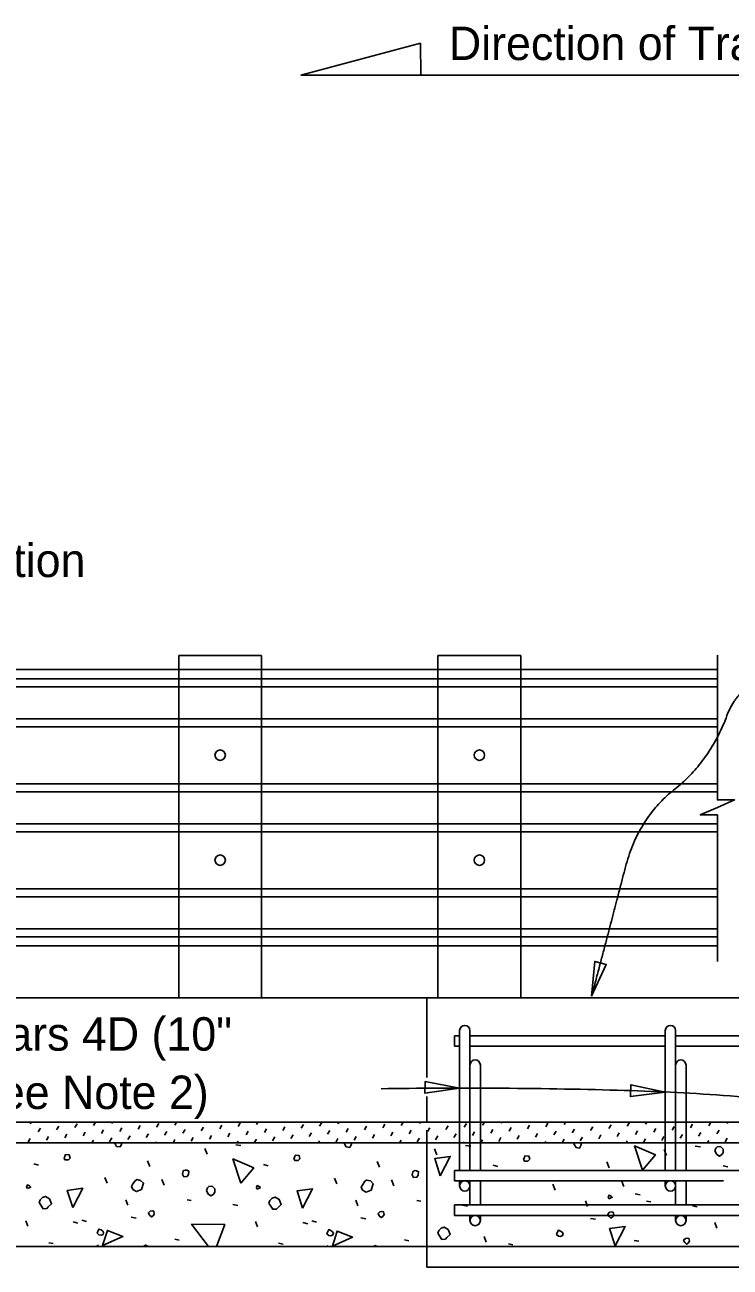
# Model space of a CAD drawing. Extents: x 0 to 41.1, y 0 to 25.9.
# Drawn here: x 33.37 to 37.62, y 6.24 to 13.74 of the extents above; entities that cross this region are included whole.
import ezdxf

# ---------------------------------------------------------------- set-up
doc = ezdxf.new("R2010")
doc.units = 0
for name, color, linetype in [('Dimension', 7, 'Continuous'), ('ExistSuperStruct', 7, 'Continuous'), ('Miscellaneous', 7, 'Continuous'), ('Rebar', 7, 'Continuous'), ('SteelMisc_h', 7, 'Continuous'), ('SubStrConc', 7, 'Continuous'), ('SubStrConc_h', 7, 'Continuous'), ('TextStructures', 7, 'Continuous')]:
    doc.layers.add(name, color=color, linetype=linetype)

msp = doc.modelspace()

# ---------------------------------------------------------------- linework, layer by layer
at = {"layer": 'Dimension'}
for p, q in [((35.0367, 13.433), (35.7584, 13.6246)), ((35.7584, 13.6246), (35.76, 13.433)), ((38.8471, 13.433), (35.0367, 13.433)), ((35.76, 13.433), (38.9734, 13.433))]:
    msp.add_line(p, q, dxfattribs=at)
msp.add_lwpolyline([(37.5468, 8.0879), (37.5468, 8.9711), (37.4435, 8.9711), (37.5468, 9.0161), (37.6502, 9.0611), (37.5468, 9.0611), (37.5468, 9.9341)], dxfattribs=at)
for points in [[(36.7889, 7.8777), (36.8763, 8.07), (36.8081, 8.0881)], [(35.9929, 7.3234), (35.7855, 7.3634), (35.7839, 7.2929)], [(37.2319, 7.2993), (37.0254, 7.3435), (37.0223, 7.273)]]:
    msp.add_lwpolyline(points, close=True, dxfattribs=at)
for points, degree in [([(38.2272, 9.8963), (37.7131, 9.8611), (37.5023, 9.2938), (37.0685, 8.9512), (36.9144, 8.3516), (36.7889, 7.8777)], 2), ([(38.4751, 7.1982), (37.7447, 7.2724), (37.1209, 7.3194), (35.9507, 7.3277), (35.5209, 7.3197)], 3)]:
    msp.add_open_spline(points, degree=degree, dxfattribs=at)
at = {"layer": 'ExistSuperStruct'}
for p, q in [((27.6853, 7.8689), (35.7954, 7.8689)), ((39.26, 7.1191), (27.6853, 7.1191)), ((27.6853, 6.994), (39.26, 6.994)), ((39.26, 6.369), (32.9053, 6.369))]:
    msp.add_line(p, q, dxfattribs=at)
at = {"layer": 'Miscellaneous'}
for p, q in [((34.2999, 9.9315), (34.2999, 7.869)), ((34.2999, 9.9315), (34.7999, 9.9315)), ((34.7999, 9.9315), (34.7999, 7.869)), ((35.8624, 9.9315), (35.8624, 7.869)), ((35.8624, 9.9315), (36.3624, 9.9315)), ((36.3624, 9.9315), (36.3624, 7.869)), ((26.2319, 9.7925), (37.5468, 9.7925)), ((26.2319, 9.7443), (37.5468, 9.7443)), ((26.2319, 9.5515), (37.5468, 9.5515)), ((26.2319, 9.5032), (37.5468, 9.5032)), ((26.2319, 9.1593), (37.5468, 9.1593)), ((26.2319, 9.1111), (37.5468, 9.1111)), ((26.2319, 8.9182), (37.5468, 8.9182)), ((26.2319, 8.8701), (37.5468, 8.8701)), ((26.2319, 8.5262), (37.5468, 8.5262)), ((26.2319, 8.4779), (37.5468, 8.4779)), ((26.2319, 8.2851), (37.5468, 8.2851)), ((26.2319, 8.2369), (37.5468, 8.2369)), ((33.4048, 7.108), (33.4112, 7.1191)), ((33.7856, 7.0981), (33.7977, 7.1191)), ((33.8962, 7.1111), (33.9008, 7.1191)), ((34.2769, 7.1011), (34.2873, 7.1191)), ((34.3876, 7.1141), (34.3904, 7.1191)), ((34.7683, 7.1041), (34.7769, 7.1191)), ((34.8789, 7.1171), (34.8801, 7.1191)), ((35.2597, 7.1072), (35.2666, 7.1191)), ((35.6404, 7.0972), (35.653, 7.1191)), ((35.751, 7.1102), (35.7562, 7.1191)), ((36.1318, 7.1002), (36.1427, 7.1191)), ((36.2424, 7.1132), (36.2458, 7.1191)), ((36.6231, 7.1032), (36.6323, 7.1191)), ((36.7338, 7.1162), (36.7354, 7.1191)), ((37.1145, 7.1063), (37.1219, 7.1191)), ((37.4952, 7.0963), (37.5082, 7.1187)), ((37.6058, 7.1093), (37.6115, 7.1191)), ((33.4537, 7.0592), (33.4666, 7.0816)), ((33.5643, 7.0722), (33.5773, 7.0946)), ((33.6131, 7.0233), (33.6261, 7.0457)), ((33.6749, 7.0851), (33.6879, 7.1075)), ((33.7238, 7.0363), (33.7367, 7.0587)), ((33.8344, 7.0493), (33.8474, 7.0717)), ((33.945, 7.0622), (33.958, 7.0846)), ((34.0557, 7.0752), (34.0686, 7.0976)), ((34.1045, 7.0264), (34.1175, 7.0487)), ((34.1663, 7.0881), (34.1793, 7.1105)), ((34.2151, 7.0393), (34.2281, 7.0617)), ((34.3258, 7.0523), (34.3387, 7.0747)), ((34.4364, 7.0652), (34.4494, 7.0876)), ((34.547, 7.0782), (34.56, 7.1006)), ((34.5959, 7.0294), (34.6088, 7.0518)), ((34.6577, 7.0912), (34.6706, 7.1136)), ((34.7065, 7.0423), (34.7195, 7.0647)), ((34.8171, 7.0553), (34.8301, 7.0777)), ((34.9278, 7.0683), (34.9407, 7.0907)), ((35.0384, 7.0812), (35.0514, 7.1036)), ((35.0872, 7.0324), (35.1002, 7.0548)), ((35.149, 7.0942), (35.162, 7.1166)), ((35.1979, 7.0454), (35.2108, 7.0677)), ((35.3085, 7.0583), (35.3215, 7.0807)), ((35.4191, 7.0713), (35.4321, 7.0937)), ((35.468, 7.0224), (35.4809, 7.0448)), ((35.5298, 7.0842), (35.5427, 7.1066)), ((35.5786, 7.0354), (35.5916, 7.0578)), ((35.6892, 7.0484), (35.7022, 7.0708)), ((35.7999, 7.0613), (35.8128, 7.0837)), ((35.9105, 7.0743), (35.9234, 7.0967)), ((35.9593, 7.0255), (35.9723, 7.0479)), ((36.0211, 7.0873), (36.0341, 7.1097)), ((36.07, 7.0384), (36.0829, 7.0608)), ((36.1806, 7.0514), (36.1935, 7.0738)), ((36.2912, 7.0644), (36.3042, 7.0867)), ((36.4019, 7.0773), (36.4148, 7.0997)), ((36.4507, 7.0285), (36.4636, 7.0509)), ((36.5125, 7.0903), (36.5254, 7.1127)), ((36.5613, 7.0415), (36.5743, 7.0638)), ((36.672, 7.0544), (36.6849, 7.0768)), ((36.7826, 7.0674), (36.7955, 7.0898)), ((36.8932, 7.0803), (36.9062, 7.1027)), ((36.9421, 7.0315), (36.955, 7.0539)), ((37.0039, 7.0933), (37.0168, 7.1157)), ((37.0527, 7.0445), (37.0656, 7.0669)), ((37.1633, 7.0574), (37.1763, 7.0798)), ((37.274, 7.0704), (37.2869, 7.0928)), ((37.3228, 7.0216), (37.3357, 7.044)), ((37.3846, 7.0834), (37.3975, 7.1058)), ((37.4334, 7.0345), (37.4464, 7.0569)), ((37.5441, 7.0475), (37.557, 7.0699)), ((33.3919, 6.9974), (33.4048, 7.0198)), ((33.5025, 7.0104), (33.5155, 7.0328)), ((33.6733, 6.994), (33.6749, 6.9969)), ((33.7764, 6.994), (33.7856, 7.0099)), ((33.8832, 7.0004), (33.8962, 7.0228)), ((33.9939, 7.0134), (34.0068, 7.0358)), ((34.1629, 6.994), (34.1663, 6.9999)), ((34.266, 6.994), (34.2769, 7.0129)), ((34.3746, 7.0034), (34.3876, 7.0258)), ((34.4852, 7.0164), (34.4982, 7.0388)), ((34.6436, 6.981), (34.6755, 6.9774)), ((34.6525, 6.994), (34.6577, 7.0029)), ((34.7556, 6.994), (34.7683, 7.0159)), ((34.866, 7.0065), (34.8789, 7.0289)), ((34.9766, 7.0194), (34.9896, 7.0418)), ((35.1421, 6.994), (35.149, 7.0059)), ((35.2467, 6.9965), (35.2597, 7.0189)), ((35.3573, 7.0095), (35.3703, 7.0319)), ((35.5286, 6.994), (35.5298, 6.996)), ((35.6317, 6.994), (35.6404, 7.009)), ((35.7381, 6.9995), (35.751, 7.0219)), ((35.8487, 7.0125), (35.8617, 7.0349)), ((36.0182, 6.994), (36.0211, 6.999)), ((36.0283, 6.9774), (36.0601, 6.9739)), ((36.1213, 6.994), (36.1318, 7.012)), ((36.2294, 7.0026), (36.2424, 7.025)), ((36.3401, 7.0155), (36.353, 7.0379)), ((36.5078, 6.994), (36.5125, 7.002)), ((36.611, 6.994), (36.6231, 7.015)), ((36.7208, 7.0056), (36.7338, 7.028)), ((36.8314, 7.0185), (36.8444, 7.0409)), ((36.9975, 6.994), (37.0039, 7.0051)), ((37.1015, 6.9956), (37.1145, 7.018)), ((37.2122, 7.0086), (37.2251, 7.031)), ((37.3839, 6.994), (37.3846, 6.9951)), ((37.413, 6.9739), (37.4448, 6.9704)), ((37.4871, 6.994), (37.4952, 7.0081)), ((37.5929, 6.9987), (37.6058, 7.021)), ((34.471, 6.925), (34.4569, 6.9604)), ((35.8557, 6.9215), (35.8416, 6.9568)), ((37.2404, 6.918), (37.2262, 6.9533)), ((33.4269, 6.8661), (33.4552, 6.859)), ((34.1252, 6.8502), (34.111, 6.8855)), ((34.8116, 6.8625), (34.8399, 6.8555)), ((35.5099, 6.8466), (35.4957, 6.882)), ((36.1963, 6.859), (36.2245, 6.8519)), ((36.8945, 6.8431), (36.8804, 6.8784)), ((37.5809, 6.8555), (37.6092, 6.8484)), ((33.8689, 6.7494), (33.8547, 6.7847)), ((34.2129, 6.7376), (34.1988, 6.773)), ((35.2535, 6.7459), (35.2394, 6.7812)), ((35.5976, 6.7341), (35.5835, 6.7695)), ((36.5698, 6.7081), (36.5556, 6.7434)), ((36.9823, 6.7306), (36.9682, 6.7659)), ((37.0508, 6.6858), (37.0809, 6.6805)), ((33.9944, 6.6168), (33.982, 6.6504)), ((34.3508, 6.6493), (34.3756, 6.6457)), ((34.6266, 6.621), (34.6566, 6.6157)), ((35.379, 6.6133), (35.3667, 6.6469)), ((35.7355, 6.6457), (35.7603, 6.6422)), ((36.0113, 6.6174), (36.0413, 6.6121)), ((36.7637, 6.6097), (36.7513, 6.6433)), ((37.1202, 6.6422), (37.1449, 6.6387)), ((37.396, 6.6139), (37.426, 6.6086)), ((33.3904, 6.4902), (33.378, 6.5237)), ((33.7168, 6.5267), (33.7451, 6.5196)), ((34.0132, 6.545), (34.0432, 6.5397)), ((34.7751, 6.4866), (34.7627, 6.5202)), ((35.1015, 6.5231), (35.1298, 6.516)), ((35.3979, 6.5414), (35.4279, 6.5361)), ((36.7825, 6.5379), (36.8126, 6.5326)), ((33.6644, 6.5167), (33.6927, 6.5096)), ((35.0491, 6.5131), (35.0774, 6.5061)), ((37.5444, 6.4796), (37.5321, 6.5131)), ((33.5177, 6.3912), (33.5442, 6.3859)), ((33.8137, 6.369), (33.8105, 6.3776)), ((34.2766, 6.4124), (34.3031, 6.4071)), ((34.9024, 6.3876), (34.9289, 6.3823)), ((35.1971, 6.369), (35.1952, 6.3741)), ((35.6613, 6.4088), (35.6878, 6.4035)), ((36.1541, 6.3946), (36.1417, 6.4282)), ((36.287, 6.3841), (36.3136, 6.3788)), ((36.5805, 6.369), (36.5799, 6.3706)), ((37.0459, 6.4053), (37.0725, 6.4))]:
    msp.add_line(p, q, dxfattribs=at)
for points in [[(33.9136, 6.994), (33.9166, 6.988)], [(33.9166, 6.988), (33.9254, 6.9721), (33.9466, 6.9686), (33.9555, 6.9845), (33.9578, 6.994)], [(35.2985, 6.994), (35.2977, 6.9916), (35.3013, 6.9845)], [(35.3013, 6.9845), (35.3101, 6.9686), (35.3313, 6.9651), (35.3401, 6.981), (35.3434, 6.994)], [(36.6844, 6.994), (36.6824, 6.988), (36.6859, 6.981)], [(36.6859, 6.981), (36.6948, 6.9651), (36.716, 6.9615), (36.7248, 6.9774), (36.7284, 6.9916), (36.7259, 6.994)], [(37.0957, 6.8285), (37.048, 6.9753), (37.1735, 6.9205), (37.0957, 6.8285)], [(37.5322, 6.9448), (37.5428, 6.9236), (37.5605, 6.913), (37.5746, 6.9236), (37.5817, 6.9342), (37.5817, 6.9554), (37.5658, 6.9713), (37.5463, 6.9696), (37.5375, 6.9607), (37.5322, 6.9448)], [(33.6143, 6.8908), (33.6355, 6.8908), (33.6461, 6.9014), (33.6408, 6.9209), (33.6178, 6.9226), (33.6143, 6.912), (33.609, 6.9032), (33.6143, 6.8908), (33.6108, 6.8944)], [(34.6743, 6.75), (34.6266, 6.8967), (34.7521, 6.8419), (34.6743, 6.75)], [(34.999, 6.8873), (35.0202, 6.8873), (35.0308, 6.8979), (35.0255, 6.9173), (35.0025, 6.9191), (34.999, 6.9085), (34.9937, 6.8997), (34.999, 6.8873), (34.9954, 6.8908)], [(35.8765, 6.7947), (35.8429, 6.899), (35.9366, 6.9113), (35.8765, 6.7947)], [(36.3836, 6.8837), (36.4049, 6.8837), (36.4155, 6.8944), (36.4102, 6.9138), (36.3872, 6.9156), (36.3836, 6.905), (36.3783, 6.8961), (36.3836, 6.8837), (36.3801, 6.8873)], [(34.3225, 6.8048), (34.3314, 6.7889), (34.3508, 6.7907), (34.3597, 6.8031), (34.3614, 6.8225), (34.3491, 6.8278), (34.3402, 6.8296), (34.3296, 6.826), (34.3261, 6.8225), (34.3225, 6.8048)], [(35.7072, 6.8013), (35.7161, 6.7854), (35.7355, 6.7871), (35.7443, 6.7995), (35.7461, 6.819), (35.7337, 6.8243), (35.7249, 6.826), (35.7143, 6.8225), (35.7108, 6.819), (35.7072, 6.8013)], [(34.0226, 6.7123), (34.0456, 6.6999), (34.0757, 6.7123), (34.0881, 6.7494), (34.0704, 6.7671), (34.0474, 6.7724), (34.0368, 6.7653), (34.0244, 6.7459), (34.0156, 6.7299), (34.0226, 6.7123)], [(35.4073, 6.7087), (35.4303, 6.6964), (35.4604, 6.7087), (35.4727, 6.7459), (35.4551, 6.7635), (35.4321, 6.7688), (35.4215, 6.7618), (35.4091, 6.7423), (35.4003, 6.7264), (35.4073, 6.7087)], [(33.3886, 6.7182), (33.4081, 6.727), (33.401, 6.7341), (33.3886, 6.7394), (33.3833, 6.727), (33.3886, 6.7182)], [(33.4594, 6.6333), (33.4823, 6.5962), (33.5053, 6.598), (33.5142, 6.6068), (33.5336, 6.6263), (33.5212, 6.6563), (33.4965, 6.6705), (33.4788, 6.6634), (33.4647, 6.6493), (33.4594, 6.6333)], [(33.662, 6.6027), (33.6284, 6.707), (33.7221, 6.7193), (33.662, 6.6027)], [(34.4675, 6.7058), (34.4781, 6.6846), (34.4958, 6.674), (34.5099, 6.6846), (34.517, 6.6952), (34.517, 6.7164), (34.5011, 6.7323), (34.4816, 6.7306), (34.4728, 6.7217), (34.4675, 6.7058)], [(34.7733, 6.7147), (34.7928, 6.7235), (34.7857, 6.7306), (34.7733, 6.7359), (34.768, 6.7235), (34.7733, 6.7147)], [(35.0467, 6.5991), (35.0131, 6.7034), (35.1068, 6.7158), (35.0467, 6.5991)], [(36.8939, 6.6569), (36.9133, 6.6658), (36.9063, 6.6728), (36.8939, 6.6781), (36.8886, 6.6658), (36.8939, 6.6569)], [(34.844, 6.6298), (34.867, 6.5927), (34.89, 6.5945), (34.8988, 6.6033), (34.9183, 6.6227), (34.9059, 6.6528), (34.8812, 6.6669), (34.8635, 6.6599), (34.8493, 6.6457), (34.844, 6.6298)], [(34.1246, 6.5573), (34.1352, 6.5467), (34.1458, 6.5538), (34.1528, 6.5644), (34.1493, 6.5821), (34.1405, 6.5838), (34.1281, 6.5821), (34.1175, 6.5715), (34.1246, 6.5573)], [(35.5092, 6.5538), (35.5198, 6.5432), (35.5304, 6.5503), (35.5375, 6.5609), (35.534, 6.5785), (35.5251, 6.5803), (35.5128, 6.5785), (35.5022, 6.5679), (35.5092, 6.5538)], [(36.8939, 6.5503), (36.9045, 6.5397), (36.9151, 6.5467), (36.9222, 6.5573), (36.9187, 6.575), (36.9098, 6.5768), (36.8974, 6.575), (36.8868, 6.5644), (36.8939, 6.5503)], [(33.8194, 6.4383), (33.8317, 6.4365), (33.8441, 6.4418), (33.8476, 6.4524), (33.8423, 6.4612), (33.8317, 6.4683), (33.8194, 6.4736), (33.8123, 6.4595), (33.8087, 6.4489), (33.8194, 6.4383)], [(33.8417, 6.3735), (33.87, 6.4654), (33.9637, 6.4283), (33.8417, 6.3735)], [(34.4788, 6.369), (34.3773, 6.5025), (34.5771, 6.5008), (34.5278, 6.369)], [(35.204, 6.4347), (35.2164, 6.433), (35.2288, 6.4383), (35.2323, 6.4489), (35.227, 6.4577), (35.2164, 6.4648), (35.204, 6.4701), (35.197, 6.4559), (35.1934, 6.4453), (35.204, 6.4347)], [(35.2264, 6.3699), (35.2547, 6.4619), (35.3484, 6.4248), (35.2264, 6.3699)], [(35.8621, 6.4487), (35.8851, 6.4116), (35.908, 6.4133), (35.9169, 6.4222), (35.9363, 6.4416), (35.924, 6.4717), (35.8992, 6.4858), (35.8815, 6.4787), (35.8674, 6.4646), (35.8621, 6.4487)], [(36.5887, 6.4312), (36.6011, 6.4294), (36.6135, 6.4347), (36.617, 6.4453), (36.6117, 6.4542), (36.6011, 6.4612), (36.5887, 6.4666), (36.5816, 6.4524), (36.5781, 6.4418), (36.5887, 6.4312)], [(36.9305, 6.373), (36.8969, 6.4773), (36.9906, 6.4897), (36.9305, 6.373)], [(34.1141, 6.369), (34.1139, 6.3699), (34.0998, 6.377), (34.0864, 6.369)], [(35.4935, 6.369), (35.4845, 6.3735), (35.477, 6.369)], [(36.8711, 6.369), (36.8692, 6.3699), (36.8676, 6.369)], [(37.3504, 6.3928), (37.361, 6.3822), (37.3716, 6.3893), (37.3787, 6.3999), (37.3752, 6.4176), (37.3663, 6.4193), (37.354, 6.4176), (37.3434, 6.407), (37.3504, 6.3928)]]:
    msp.add_lwpolyline(points, dxfattribs=at)
at = {"layer": 'Rebar'}
for p, q in [((35.9933, 7.671), (35.9933, 6.8272)), ((36.0558, 6.8272), (36.0558, 7.671)), ((37.2329, 7.671), (37.2329, 6.8272)), ((37.2954, 6.8272), (37.2954, 7.671)), ((35.9621, 7.6398), (35.9933, 7.6398)), ((35.9621, 7.6398), (35.9621, 7.5773)), ((35.9621, 7.5773), (35.9933, 7.5773)), ((36.0558, 7.6398), (37.2329, 7.6398)), ((36.0558, 7.5773), (37.2329, 7.5773)), ((37.2954, 7.6398), (38.4725, 7.6398)), ((37.2954, 7.5773), (38.4725, 7.5773)), ((36.1183, 6.8272), (36.1183, 7.4627)), ((37.3579, 6.8272), (37.3579, 7.4627)), ((35.9621, 6.8272), (35.9621, 6.7647)), ((35.9621, 6.8272), (38.6287, 6.8272)), ((35.9621, 6.7647), (37.5835, 6.7647)), ((35.9933, 6.7647), (35.9933, 6.7335)), ((36.0558, 6.6189), (36.0558, 6.7647)), ((36.1183, 6.6189), (36.1183, 6.7647)), ((37.2329, 6.7647), (37.2329, 6.7335)), ((37.2954, 6.6189), (37.2954, 6.7647)), ((37.3579, 6.6189), (37.3579, 6.7647)), ((35.9621, 6.6189), (35.9621, 6.5564)), ((35.9621, 6.6189), (38.6287, 6.6189)), ((35.9621, 6.5564), (38.6287, 6.5564)), ((36.0558, 6.5252), (36.0558, 6.5564)), ((36.1183, 6.5252), (36.1183, 6.5564)), ((37.2954, 6.5252), (37.2954, 6.5564)), ((37.3579, 6.5252), (37.3579, 6.5564))]:
    msp.add_line(p, q, dxfattribs=at)
for centre in [(36.0245, 6.7335), (37.2641, 6.7335), (36.087, 6.5252), (37.3266, 6.5252)]:
    msp.add_circle(centre, 0.0312, dxfattribs=at)
for centre, radius, start, end in [((36.0245, 7.671), 0.0312, 0, 180), ((37.2641, 7.671), 0.0312, 0, 180), ((36.087, 7.4627), 0.0312, 0, 180), ((37.3266, 7.4627), 0.0312, 0, 180), ((36.2545, 5.8272), 1, 90, 90.00000277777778)]:
    msp.add_arc(centre, radius, start, end, dxfattribs=at)
at = {"layer": 'SteelMisc_h'}
for p, q in [((37.5468, 9.848), (26.2319, 9.848)), ((37.5468, 8.1814), (26.2319, 8.1814))]:
    msp.add_line(p, q, dxfattribs=at)
for centre in [(34.5499, 9.3314), (36.1124, 9.3314), (34.5499, 8.6982), (36.1124, 8.6982)]:
    msp.add_circle(centre, 0.0312, dxfattribs=at)
at = {"layer": 'SubStrConc'}
for p, q in [((35.7954, 7.8689), (38.7954, 7.8689)), ((35.7954, 7.3877), (35.7954, 7.8689)), ((35.7954, 7.119), (35.7954, 7.2721))]:
    msp.add_line(p, q, dxfattribs=at)
at = {"layer": 'SubStrConc_h'}
for p, q in [((35.7954, 7.119), (38.7954, 7.119)), ((35.7954, 6.2439), (35.7954, 7.0704)), ((35.7954, 6.2439), (38.7954, 6.2439))]:
    msp.add_line(p, q, dxfattribs=at)

# ---------------------------------------------------------------- texts
at = {"layer": 'Dimension'}
for s, p in [('Roadway Guardrail Transition', (30.1716, 10.4055)), ('Double Dowel Bars 4D (10" ', (31.3343, 7.5496)), ('Embedment) (See Note 2)', (31.3343, 7.1976))]:
    msp.add_text(s, height=0.2016, dxfattribs=at).set_placement(p)
at = {"layer": 'TextStructures'}
msp.add_text('Direction of Traffic', height=0.2016, rotation=359.99977, dxfattribs=at).set_placement((35.9286, 13.5233))

doc.saveas('drawing.dxf')
